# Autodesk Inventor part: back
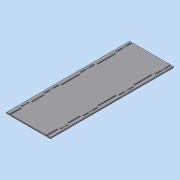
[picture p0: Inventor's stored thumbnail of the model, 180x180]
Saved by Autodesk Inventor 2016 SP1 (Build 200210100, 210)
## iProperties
Created: 2016-06
Part Number: back
Material: Generic
Document SubType Name: Modeling
Designer: Mohamed A.
Density: 1 g/cm^3
Appearance: Default
Author: Mohamed A.
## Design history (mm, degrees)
sketch "Sketch1"
  geometry: L1 (-57, 160)-(57, 160); L2 (57, 160)-(57, -160); L3 (57, -160)-(-57, -160); L4 (-57, -160)-(-57, 160); L5 (-57, 160)-(57, -160); L6 (57, 160)-(-57, -160); 1 further point
  constraints: 12 end point, 2 midpoint, 2 parallel, 1 horizontal, 1 perpendicular
  dimensions: "d0" = 114 distance of L2.end L3.end; "d1" = 320 distance of L1.end L2.end
extrude "Extrusion1" new body sketch "Sketch1" distance "d2" = 3; taper "d3" = 0 deg
sketch "Sketch2"
  geometry: L1 (52, 140.75)-(52, 137.65) reference; L2 (52, 140.75)-(49, 140.75) reference; L3 (49, 137.65)-(49, 140.75) reference; L4 (52, 137.65)-(49, 137.65) reference; L5 (52, 45.05)-(52, 41.95) reference; L6 (52, 45.05)-(49, 45.05) reference; L7 (49, 41.95)-(49, 45.05) reference; L8 (52, 41.95)-(49, 41.95) reference; L9 (-49, 45.05)-(-49, 41.95) reference; L10 (-49, 45.05)-(-52, 45.05) reference; L11 (-52, 41.95)-(-52, 45.05) reference; L12 (-49, 41.95)-(-52, 41.95) reference; L13 (-49, 140.75)-(-49, 137.65) reference; L14 (-49, 140.75)-(-52, 140.75) reference; L15 (-52, 137.65)-(-52, 140.75) reference; L16 (-49, 137.65)-(-52, 137.65) reference; L17 (52, -48.15)-(52, -51.25) reference; L18 (52, -48.15)-(49, -48.15) reference; L19 (49, -51.25)-(49, -48.15) reference; L20 (52, -51.25)-(49, -51.25) reference; L21 (-49, -48.15)-(-49, -51.25) reference; L22 (-49, -48.15)-(-52, -48.15) reference; L23 (-52, -51.25)-(-52, -48.15) reference; L24 (-49, -51.25)-(-52, -51.25) reference; L25 (52, -116.45)-(52, -119.55) reference; L26 (52, -116.45)-(49, -116.45) reference; L27 (49, -119.55)-(49, -116.45) reference; L28 (52, -119.55)-(49, -119.55) reference; L29 (-49, -116.45)-(-49, -119.55) reference; L30 (-49, -116.45)-(-52, -116.45) reference; L31 (-52, -119.55)-(-52, -116.45) reference; L32 (-49, -119.55)-(-52, -119.55) reference; L33 (-49, -114.25)-(-52, -114.25) reference; L34 (-52, -114.25)-(-52, -109) reference; L35 (-52, -109)-(-49, -109) reference; L36 (-49, -109)-(-49, -114.25) reference; L37 (-52, -121.75)-(-49, -121.75) reference; L38 (-49, -121.75)-(-49, -127) reference; L39 (-49, -127)-(-52, -127) reference; L40 (-52, -127)-(-52, -121.75) reference; L41 (-52, 39)-(-49, 39) reference; L42 (-49, 39)-(-49, 25.2) reference; L43 (-49, 25.2)-(-52, 25.2) reference; L44 (-52, 25.2)-(-52, 39) reference; L45 (-49, 48)-(-52, 48) reference; L46 (-52, 48)-(-52, 61.8) reference; L47 (-52, 61.8)-(-49, 61.8) reference; L48 (-49, 61.8)-(-49, 48) reference; L49 (-52, 134.7)-(-49, 134.7) reference; L50 (-49, 134.7)-(-49, 118.4) reference; L51 (-49, 118.4)-(-52, 118.4) reference; L52 (-52, 118.4)-(-52, 134.7) reference; L53 (-49, 143.7)-(-52, 143.7) reference; L54 (-52, 143.7)-(-52, 160) reference; L55 (-52, 160)-(-49, 160) reference; L56 (-49, 160)-(-49, 143.7) reference; L57 (-52, -54.2)-(-49, -54.2) reference; L58 (-49, -54.2)-(-49, -68) reference; L59 (-49, -68)-(-52, -68) reference; L60 (-52, -68)-(-52, -54.2) reference; L61 (-49, -45.2)-(-52, -45.2) reference; L62 (-52, -45.2)-(-52, -31.4) reference; L63 (-52, -31.4)-(-49, -31.4) reference; L64 (-49, -31.4)-(-49, -45.2) reference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; C1 r 1.4 at (50.5, 139.2); C2 r 1.4 at (-50.5, 139.2); C3 r 1.4 at (-50.5, 43.5); C4 r 1.4 at (50.5, 43.5); C5 r 1.4 at (50.5, -49.7); C6 r 1.4 at (-50.5, -49.7); C7 r 1.4 at (50.5, -118); C8 r 1.4 at (-50.5, -118)
  constraints: 224 end point, 56 horizontal, 56 vertical, 8 centre point, 112 other
  dimensions: "d10" = 2.8 diameter of C1; "d11" = 2.8 diameter of C2; "d12" = 2.8 diameter of C3; "d13" = 2.8 diameter of C4; "d14" = 2.8 diameter of C5; "d15" = 2.8 diameter of C6; "d16" = 2.8 diameter of C7; "d17" = 2.8 diameter of C8
extrude "Extrusion2" cut sketch "Sketch2" distance "d8" = 10; taper "d9" = 0 deg
body "Solid1"
node "Reference6"
node "Reference7"
node "Reference8"
node "Reference9"
node "Reference10"
node "Reference11"
node "Reference12"
node "Reference13"
